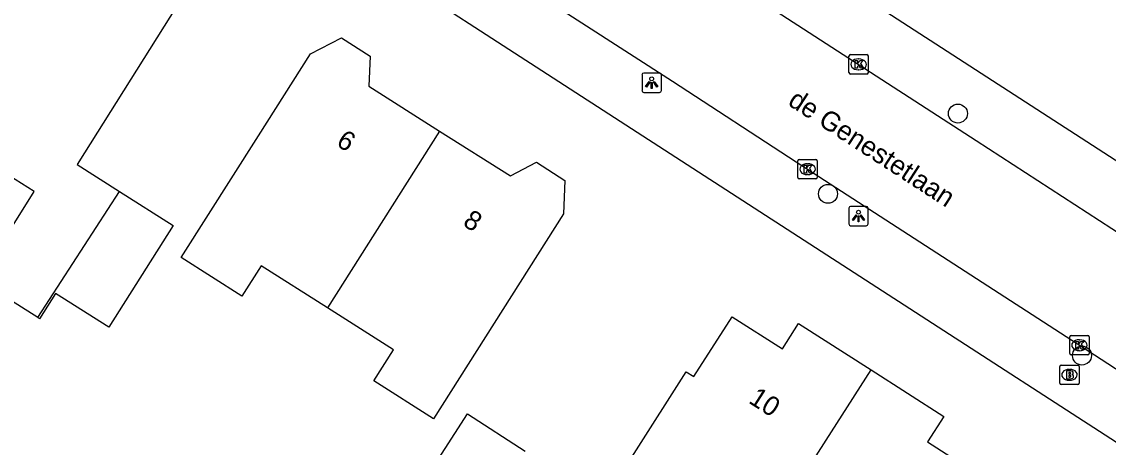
# Model space of a CAD drawing. Extents: x 161141 to 161601, y 381708 to 382245.
# Drawn here: x 161326.4 to 161382.4, y 382024.5 to 382046.4 of the extents above; entities that cross this region are included whole.
import ezdxf

# ---------------------------------------------------------------- set-up
doc = ezdxf.new("R2010")
doc.units = 0
for name, color, linetype in [('IMGEO_Boom', 7, 'Continuous'), ('IMGEO_Brandkraan', 7, 'Continuous'), ('IMGEO_Kolk', 7, 'Continuous'), ('IMGEO_Lichtpunt', 7, 'Continuous'), ('IMGEO_Openbare_ruimte_label', 7, 'Continuous'), ('IMGEO_Pand', 7, 'Continuous'), ('IMGEO_Pand_nummerreeks', 7, 'Continuous'), ('IMGEO_Rijbaan_lokaal_open', 7, 'Continuous'), ('IMGEO_Voetpad_open', 7, 'Continuous')]:
    doc.layers.add(name, color=color, linetype=linetype)

msp = doc.modelspace()

# ---------------------------------------------------------------- linework, layer by layer
at = {"layer": 'IMGEO_Boom'}
for centre in [(161374.648, 382041.67), (161367.953, 382037.533), (161381.04, 382029.2)]:
    msp.add_circle(centre, 0.489, dxfattribs=at)
at = {"layer": 'IMGEO_Brandkraan'}
for p, q in [((161379.895, 382027.782), (161379.895, 382028.634)), ((161379.97, 382028.708), (161380.822, 382028.708)), ((161380.896, 382028.634), (161380.896, 382027.782)), ((161380.383, 382028.488), (161380.408, 382028.488)), ((161380.822, 382027.708), (161379.97, 382027.708)), ((161380.406, 382027.928), (161380.381, 382027.928))]:
    msp.add_line(p, q, dxfattribs=at)
for points in [[(161379.895, 382027.782), (161379.895, 382028.634)], [(161379.97, 382028.708), (161380.822, 382028.708)], [(161380.896, 382028.634), (161380.896, 382027.782)], [(161380.243, 382028.408), (161380.243, 382028.008), (161380.456, 382028.008)], [(161380.474, 382028.408), (161380.243, 382028.408)], [(161380.422, 382028.327), (161380.368, 382028.327), (161380.368, 382028.251)], [(161380.368, 382028.251), (161380.421, 382028.251)], [(161380.43, 382028.175), (161380.368, 382028.175), (161380.368, 382028.094)], [(161380.368, 382028.094), (161380.43, 382028.094)], [(161380.822, 382027.708), (161379.97, 382027.708)]]:
    msp.add_lwpolyline(points, dxfattribs=at)
for centre, radius, start, end in [((161379.972, 382028.632), 0.0765, 91.552, 178.448), ((161379.972, 382028.632), 0.0765, 91.552, 178.448), ((161380.82, 382028.632), 0.0765, 1.552, 88.448), ((161380.82, 382028.632), 0.0765, 1.552, 88.448), ((161380.423, 382028.289), 0.0379, 267.8285, 90.9355), ((161380.431, 382028.134), 0.0404, 269.8759, 90.5077), ((161380.478, 382028.263), 0.145, 59.4692, 91.5367), ((161380.503, 382028.31), 0.0922, 285.5137, 58.1501), ((161380.508, 382028.118), 0.105, 301.3115, 78.989), ((161379.972, 382027.784), 0.0765, 181.552, 268.448), ((161379.972, 382027.784), 0.0765, 181.552, 268.448), ((161380.462, 382028.259), 0.251, 268.6676, 293.5347), ((161380.82, 382027.784), 0.0765, 271.552, 358.448), ((161380.82, 382027.784), 0.0765, 271.552, 358.448)]:
    msp.add_arc(centre, radius, start, end, dxfattribs=at)
for centre, major_axis, ratio, start_param, end_param in [((161380.382, 382028.208), (-0.387, 0.002), 0.722429, 4.712389, 7.853982), ((161380.407, 382028.208), (-0.39, 0.002), 0.717154, 1.570796, 4.712389)]:
    msp.add_ellipse(centre, major_axis=major_axis, ratio=ratio, start_param=start_param, end_param=end_param, dxfattribs=at)
at = {"layer": 'IMGEO_Kolk'}
for p, q in [((161369.03, 382043.778), (161369.03, 382044.63)), ((161369.105, 382044.704), (161369.957, 382044.704)), ((161369.518, 382044.484), (161369.543, 382044.484)), ((161370.031, 382044.63), (161370.031, 382043.778)), ((161369.541, 382043.924), (161369.516, 382043.924)), ((161369.957, 382043.704), (161369.105, 382043.704)), ((161366.474, 382039.303), (161367.326, 382039.303)), ((161366.399, 382038.377), (161366.399, 382039.229)), ((161366.887, 382039.083), (161366.912, 382039.083)), ((161367.4, 382039.229), (161367.4, 382038.377)), ((161367.326, 382038.303), (161366.474, 382038.303)), ((161366.91, 382038.523), (161366.885, 382038.523)), ((161380.41, 382029.306), (161380.41, 382030.158)), ((161380.485, 382030.232), (161381.337, 382030.232)), ((161380.898, 382030.012), (161380.923, 382030.012)), ((161381.411, 382030.158), (161381.411, 382029.306)), ((161381.337, 382029.232), (161380.485, 382029.232)), ((161380.921, 382029.452), (161380.896, 382029.452))]:
    msp.add_line(p, q, dxfattribs=at)
for points in [[(161369.03, 382043.778), (161369.03, 382044.63)], [(161369.105, 382044.704), (161369.957, 382044.704)], [(161369.351, 382044.404), (161369.474, 382044.404), (161369.474, 382044.253), (161369.604, 382044.404), (161369.768, 382044.404), (161369.622, 382044.253), (161369.775, 382044.004), (161369.623, 382044.004), (161369.538, 382044.168), (161369.474, 382044.101), (161369.474, 382044.004), (161369.351, 382044.004), (161369.351, 382044.404)], [(161370.031, 382044.63), (161370.031, 382043.778)], [(161369.957, 382043.704), (161369.105, 382043.704)], [(161366.474, 382039.303), (161367.326, 382039.303)], [(161366.399, 382038.377), (161366.399, 382039.229)], [(161366.72, 382039.003), (161366.843, 382039.003), (161366.843, 382038.852), (161366.973, 382039.003), (161367.137, 382039.003), (161366.991, 382038.852), (161367.144, 382038.603), (161366.992, 382038.603), (161366.907, 382038.767), (161366.843, 382038.7), (161366.843, 382038.603), (161366.72, 382038.603), (161366.72, 382039.003)], [(161367.4, 382039.229), (161367.4, 382038.377)], [(161367.326, 382038.303), (161366.474, 382038.303)], [(161380.41, 382029.306), (161380.41, 382030.158)], [(161380.485, 382030.232), (161381.337, 382030.232)], [(161380.731, 382029.932), (161380.854, 382029.932), (161380.854, 382029.781), (161380.984, 382029.932), (161381.148, 382029.932), (161381.002, 382029.781), (161381.155, 382029.532), (161381.003, 382029.532), (161380.918, 382029.696), (161380.854, 382029.629), (161380.854, 382029.532), (161380.731, 382029.532), (161380.731, 382029.932)], [(161381.411, 382030.158), (161381.411, 382029.306)], [(161381.337, 382029.232), (161380.485, 382029.232)]]:
    msp.add_lwpolyline(points, dxfattribs=at)
for centre, start, end in [((161369.107, 382044.628), 91.552, 178.448), ((161369.107, 382044.628), 91.552, 178.448), ((161369.955, 382044.628), 1.552, 88.448), ((161369.955, 382044.628), 1.552, 88.448), ((161369.107, 382043.78), 181.552, 268.448), ((161369.107, 382043.78), 181.552, 268.448), ((161369.955, 382043.78), 271.552, 358.448), ((161369.955, 382043.78), 271.552, 358.448), ((161366.476, 382039.227), 91.552, 178.448), ((161366.476, 382039.227), 91.552, 178.448), ((161367.324, 382039.227), 1.552, 88.448), ((161367.324, 382039.227), 1.552, 88.448), ((161366.476, 382038.379), 181.552, 268.448), ((161366.476, 382038.379), 181.552, 268.448), ((161367.324, 382038.379), 271.552, 358.448), ((161367.324, 382038.379), 271.552, 358.448), ((161380.487, 382030.156), 91.552, 178.448), ((161380.487, 382030.156), 91.552, 178.448), ((161381.335, 382030.156), 1.552, 88.448), ((161381.335, 382030.156), 1.552, 88.448), ((161380.487, 382029.308), 181.552, 268.448), ((161380.487, 382029.308), 181.552, 268.448), ((161381.335, 382029.308), 271.552, 358.448), ((161381.335, 382029.308), 271.552, 358.448)]:
    msp.add_arc(centre, 0.0765, start, end, dxfattribs=at)
for centre, major_axis, ratio, start_param, end_param in [((161369.517, 382044.204), (-0.387, 0.002), 0.722429, 4.712389, 7.853982), ((161369.542, 382044.204), (-0.39, 0.002), 0.717154, 1.570796, 4.712389), ((161366.886, 382038.803), (-0.387, 0.002), 0.722429, 4.712389, 7.853982), ((161366.911, 382038.803), (-0.39, 0.002), 0.717154, 1.570796, 4.712389), ((161380.897, 382029.732), (-0.387, 0.002), 0.722429, 4.712389, 7.853982), ((161380.922, 382029.732), (-0.39, 0.002), 0.717154, 1.570796, 4.712389)]:
    msp.add_ellipse(centre, major_axis=major_axis, ratio=ratio, start_param=start_param, end_param=end_param, dxfattribs=at)
at = {"layer": 'IMGEO_Lichtpunt'}
for p, q in [((161359.27, 382043.755), (161358.462, 382043.755)), ((161359.27, 382043.755), (161358.462, 382043.755)), ((161358.368, 382043.66), (161358.368, 382042.853)), ((161358.368, 382043.66), (161358.368, 382042.853)), ((161359.364, 382042.853), (161359.364, 382043.66)), ((161359.364, 382042.853), (161359.364, 382043.66)), ((161358.462, 382042.759), (161359.27, 382042.759)), ((161358.462, 382042.759), (161359.27, 382042.759)), ((161369.026, 382036.788), (161369.026, 382035.981)), ((161369.026, 382036.788), (161369.026, 382035.981)), ((161369.928, 382036.883), (161369.12, 382036.883)), ((161369.928, 382036.883), (161369.12, 382036.883)), ((161370.022, 382035.981), (161370.022, 382036.788)), ((161370.022, 382035.981), (161370.022, 382036.788)), ((161369.12, 382035.887), (161369.928, 382035.887)), ((161369.12, 382035.887), (161369.928, 382035.887))]:
    msp.add_line(p, q, dxfattribs=at)
for points in [[(161358.742, 382043.324), (161358.781, 382043.296), (161358.593, 382043.034), (161358.555, 382043.061), (161358.742, 382043.324)], [(161358.844, 382043.276), (161358.891, 382043.276), (161358.891, 382042.954), (161358.844, 382042.954), (161358.844, 382043.276)], [(161358.954, 382043.296), (161358.992, 382043.323), (161359.179, 382043.061), (161359.14, 382043.033), (161358.954, 382043.296)], [(161369.4, 382036.452), (161369.439, 382036.424), (161369.251, 382036.162), (161369.213, 382036.189), (161369.4, 382036.452)], [(161369.502, 382036.404), (161369.549, 382036.404), (161369.549, 382036.082), (161369.502, 382036.082), (161369.502, 382036.404)], [(161369.612, 382036.424), (161369.65, 382036.451), (161369.837, 382036.189), (161369.798, 382036.161), (161369.612, 382036.424)]]:
    msp.add_lwpolyline(points, dxfattribs=at)
for centre in [(161358.867, 382043.458), (161369.525, 382036.586)]:
    msp.add_circle(centre, 0.0994, dxfattribs=at)
for centre, start, end in [((161358.462, 382043.66), 90, 180), ((161358.462, 382043.66), 90, 180), ((161359.27, 382043.66), 0, 90), ((161359.27, 382043.66), 0, 90), ((161358.462, 382042.853), 180, 270), ((161358.462, 382042.853), 180, 270), ((161359.27, 382042.853), 270, 0), ((161359.27, 382042.853), 270, 360), ((161369.12, 382036.788), 90, 180), ((161369.12, 382036.788), 90, 180), ((161369.928, 382036.788), 0, 90), ((161369.928, 382036.788), 0, 90), ((161369.12, 382035.981), 180, 270), ((161369.12, 382035.981), 180, 270), ((161369.928, 382035.981), 270, 0), ((161369.928, 382035.981), 270, 360)]:
    msp.add_arc(centre, 0.0946, start, end, dxfattribs=at)
at = {"layer": 'IMGEO_Pand'}
for points in [[(161327.227, 382031.156), (161324.172, 382033.077), (161327.053, 382037.661), (161320.18, 382041.981), (161322.293, 382045.342), (161322.758, 382045.049), (161325.756, 382049.819), (161328.417, 382054.052), (161329.525, 382053.356), (161330.221, 382053.724), (161332.458, 382052.318), (161332.427, 382051.481), (161335.761, 382049.386), (161329.259, 382039.042), (161331.435, 382037.66)], [(161342.157, 382031.659), (161338.744, 382033.826), (161337.751, 382032.263), (161334.62, 382034.25), (161338.601, 382040.519), (161341.281, 382044.739), (161342.875, 382045.571), (161344.352, 382044.634), (161344.286, 382043.087), (161347.935, 382040.77)], [(161347.935, 382040.77), (161351.583, 382038.453), (161352.931, 382039.157), (161354.394, 382038.228), (161354.321, 382036.501), (161351.641, 382032.281), (161347.618, 382025.948), (161344.549, 382027.897), (161345.564, 382029.496), (161342.157, 382031.659)], [(161347.935, 382040.77), (161342.157, 382031.659)], [(161331.435, 382037.66), (161334.21, 382035.898), (161330.891, 382030.671), (161328.144, 382032.397), (161327.326, 382031.094), (161327.227, 382031.156)], [(161327.227, 382031.156), (161331.435, 382037.66)], [(161363.651, 382018.259), (161359.669, 382020.808), (161358.499, 382018.98), (161355.762, 382020.732), (161357.956, 382024.159), (161360.651, 382028.37), (161361.044, 382028.118), (161363.016, 382031.198), (161365.6, 382029.544), (161366.437, 382030.853), (161370.18, 382028.457)], [(161370.18, 382028.457), (161373.925, 382026.06), (161373.085, 382024.748), (161375.732, 382023.053), (161373.728, 382019.922), (161374.141, 382019.658), (161371.446, 382015.447), (161369.264, 382012.038), (161366.393, 382013.876), (161367.587, 382015.74), (161363.651, 382018.259)], [(161363.651, 382018.259), (161370.18, 382028.457)], [(161349.384, 382019.699), (161346.418, 382021.618), (161349.381, 382026.197), (161352.347, 382024.278)]]:
    msp.add_lwpolyline(points, dxfattribs=at)
at = {"layer": 'IMGEO_Rijbaan_lokaal_open'}
for points in [[(161311.536, 382081.664), (161356.674, 382052.498), (161362.411, 382048.813), (161375.585, 382040.285), (161382.572, 382035.748), (161395.928, 382027.083), (161402.927, 382022.535), (161416.852, 382013.552), (161420.042, 382011.494), (161421.741, 382010.379), (161425.551, 382007.922), (161458.647, 381986.439), (161460.91, 381984.988)], [(161480.897, 381964.849), (161471.977, 381970.646), (161450.889, 381984.377), (161443.856, 381988.93), (161430.314, 381997.713), (161423.318, 382002.239), (161408.287, 382012.005), (161402.555, 382015.697), (161398.439, 382018.395), (161388.068, 382025.069), (161381.679, 382029.228), (161366.307, 382039.161), (161359.944, 382043.32), (161345.442, 382052.667), (161339.032, 382056.795), (161328.504, 382063.628), (161325.321, 382065.668), (161306.338, 382077.878)]]:
    msp.add_lwpolyline(points, dxfattribs=at)
at = {"layer": 'IMGEO_Voetpad_open'}
for points in [[(161313.623, 382083.997), (161443.483, 382000), (161462.38, 381987.777)], [(161474.804, 381965.241), (161421.048, 382000), (161306.066, 382074.349)]]:
    msp.add_lwpolyline(points, dxfattribs=at)

# ---------------------------------------------------------------- texts
at = {"layer": 'IMGEO_Openbare_ruimte_label'}
msp.add_text('de Genestetlaan', height=1, rotation=327.041, dxfattribs=at).set_placement((161365.832, 382042.144))
at = {"layer": 'IMGEO_Pand_nummerreeks'}
for s, rotation, p in [('6', 327.7174, (161342.557, 382040.054)), ('8', 327.7174, (161349.08, 382035.933)), ('10', 327.3591, (161363.809, 382026.795))]:
    msp.add_text(s, height=1, rotation=rotation, dxfattribs=at).set_placement(p)

doc.saveas('drawing.dxf')
